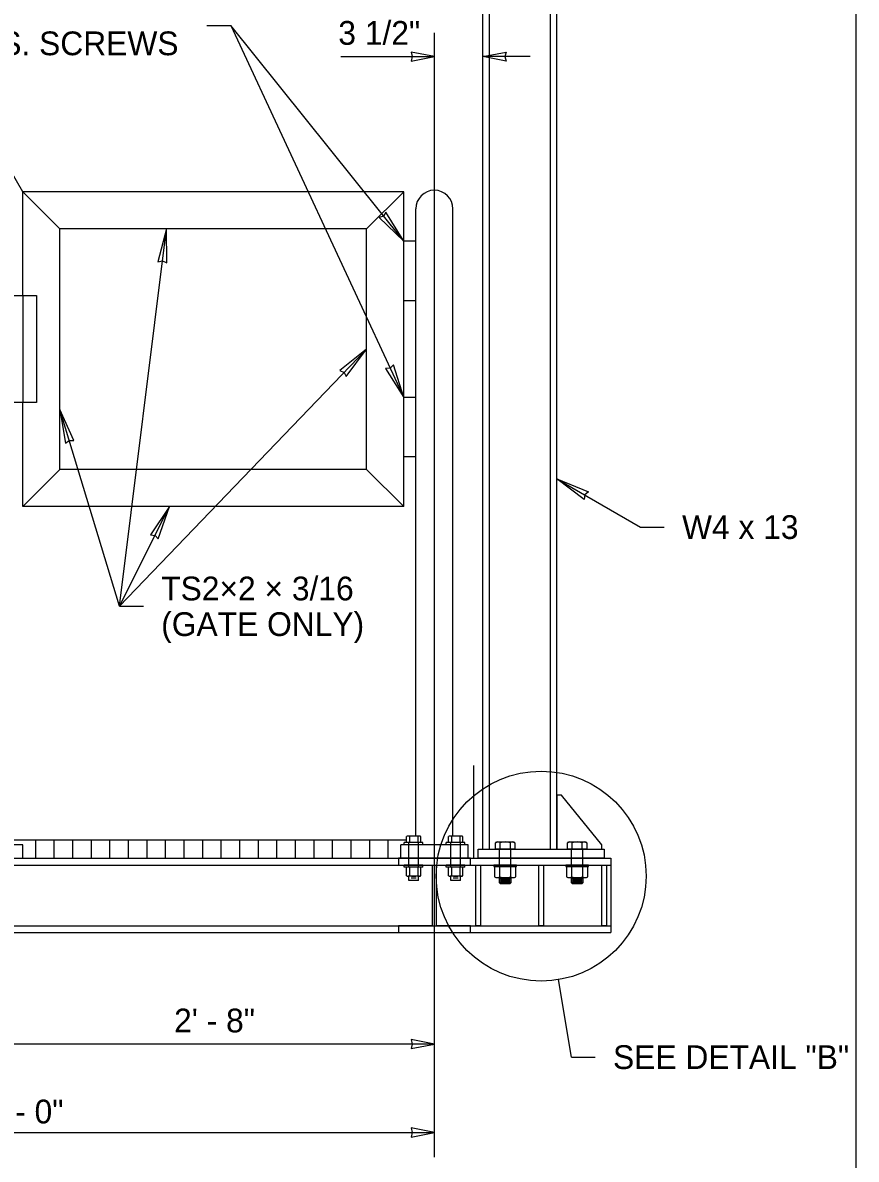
# Model space of a CAD drawing. Extents: x 99862 to 103151, y 100000 to 108076.
# Drawn here: x 102590 to 103151, y 100913 to 101679 of the extents above; entities that cross this region are included whole.
import ezdxf

# ---------------------------------------------------------------- set-up
doc = ezdxf.new("R2010")
doc.units = 0
for name, color, linetype in [('Level 1', 7, 'Continuous'), ('Level 13', 7, 'Continuous'), ('Level 15', 7, 'Continuous'), ('Level 2', 7, 'Continuous'), ('Level 20', 7, 'Continuous'), ('Level 30', 7, 'Continuous'), ('Level 36', 7, 'Continuous'), ('Level 4', 7, 'Continuous')]:
    doc.layers.add(name, color=color, linetype=linetype)

msp = doc.modelspace()

# ---------------------------------------------------------------- linework, layer by layer
at = {"layer": 'Level 1'}
msp.add_lwpolyline([(99862, 99999.5), (103151, 99999.5), (103151, 102075.5), (99862, 102075.5)], close=True, dxfattribs=at)
at = {"layer": 'Level 13'}
for p, q in [((102899.33, 101721.47), (102899.33, 101122.28)), ((102949.33, 101122.28), (102949.33, 101721.47)), ((102952.36, 101158.65), (102949.33, 101158.65)), ((102949.33, 101158.65), (102949.33, 101122.28)), ((102979.64, 101125.31), (102952.36, 101158.65)), ((102949.33, 101122.28), (102979.64, 101122.28)), ((102979.64, 101122.28), (102979.64, 101125.31)), ((102985.7, 101116.22), (102985.7, 101066.22))]:
    msp.add_line(p, q, dxfattribs=at)
msp.add_lwpolyline([(102896.3, 101122.28), (102981.15, 101122.28), (102981.15, 101116.22), (102896.3, 101116.22)], close=True, dxfattribs=at)
at = {"layer": 'Level 15'}
for p, q in [((102713.59, 101677.27), (102729.59, 101677.27)), ((102866.83, 100914.85), (102866.83, 101672.31)), ((102803.75, 101656.31), (102866.83, 101656.31)), ((102931.33, 101656.31), (102899.33, 101656.31)), ((102589.52, 101565.31), (102558.88, 101618.38)), ((102654.79, 101285.98), (102686.42, 101540.31)), ((102654.79, 101285.98), (102821.15, 101459.28)), ((102654.79, 101285.98), (102614.52, 101418.59)), ((102949.33, 101371.88), (103005.63, 101339.38)), ((102654.79, 101285.98), (102688.34, 101353.24)), ((103005.62, 101339.38), (103021.62, 101339.38)), ((102654.79, 101285.98), (102670.79, 101285.98)), ((102959.14, 100982.27), (102950.41, 101034.46)), ((102866.83, 100991.1), (102566.83, 100991.1)), ((102959.14, 100982.27), (102975.14, 100982.27)), ((102308.84, 100931.49), (102866.84, 100931.49))]:
    msp.add_line(p, q, dxfattribs=at)
msp.add_lwpolyline([(102846.15, 101531.9), (102729.59, 101677.27), (102846.15, 101426.67)], dxfattribs=at)
for points in [[(102866.84, 101656.31), (102851.11, 101659.39), (102851.84, 101656.31), (102851.11, 101653.23)], [(102899.34, 101656.31), (102915.06, 101659.39), (102914.33, 101656.31), (102915.06, 101653.23)], [(102846.15, 101531.91), (102834.2, 101551.58), (102832.53, 101548.89), (102829.54, 101547.85)], [(102686.42, 101540.31), (102680.64, 101518.02), (102683.73, 101518.7), (102686.57, 101517.29)], [(102821.15, 101459.28), (102803.18, 101444.87), (102806.07, 101443.57), (102807.49, 101440.74)], [(102846.15, 101426.67), (102839.23, 101448.63), (102836.96, 101446.41), (102833.81, 101446.11)], [(102614.52, 101418.6), (102618.3, 101395.88), (102620.85, 101397.76), (102624.01, 101397.62)], [(102949.33, 101371.88), (102970.6, 101363.05), (102968.19, 101360.99), (102967.61, 101357.88)], [(102688.34, 101353.24), (102675.48, 101334.15), (102678.62, 101333.76), (102680.82, 101331.48)], [(102866.83, 100991.1), (102851.11, 100994.18), (102851.84, 100991.1), (102851.11, 100988.01)], [(102866.83, 100931.49), (102851.11, 100934.58), (102851.84, 100931.49), (102851.11, 100928.41)]]:
    msp.add_lwpolyline(points, close=True, dxfattribs=at)
msp.add_circle((102938.75, 101104.21), 70.72, dxfattribs=at)
at = {"layer": 'Level 2'}
for p, q in [((102589.52, 101565.31), (102614.52, 101540.31)), ((102846.15, 101565.31), (102821.15, 101540.31))]:
    msp.add_line(p, q, dxfattribs=at)
at = {"layer": 'Level 30'}
for p, q in [((102911.21, 101122.28), (102911.21, 101126.69)), ((102917.76, 101126.69), (102917.76, 101122.28)), ((102959.69, 101122.28), (102959.69, 101126.69)), ((102966.25, 101126.69), (102966.25, 101122.28)), ((102910.93, 101103.75), (102910.93, 101110.65)), ((102918.04, 101110.65), (102918.04, 101103.75)), ((102959.42, 101103.75), (102959.42, 101110.65)), ((102966.53, 101110.65), (102966.53, 101103.75)), ((102909.16, 101103.19), (102919.82, 101103.19)), ((102910.7, 101102.48), (102918.27, 101102.48)), ((102910.7, 101101.06), (102918.27, 101101.06)), ((102918.27, 101099.64), (102910.7, 101099.64)), ((102911.41, 101101.77), (102917.56, 101101.77)), ((102911.41, 101100.35), (102917.56, 101100.35)), ((102957.64, 101103.19), (102968.3, 101103.19)), ((102959.18, 101102.48), (102966.76, 101102.48)), ((102959.18, 101101.06), (102966.76, 101101.06)), ((102966.76, 101099.64), (102959.18, 101099.64)), ((102959.89, 101101.77), (102966.05, 101101.77)), ((102959.89, 101100.35), (102966.05, 101100.35))]:
    msp.add_line(p, q, dxfattribs=at)
for points in [[(102920.17, 101127.25), (102921.05, 101126.75), (102921.05, 101122.28), (102907.92, 101122.28), (102907.92, 101126.75), (102908.8, 101127.25), (102920.17, 101127.25)], [(102968.65, 101127.25), (102969.53, 101126.75), (102969.53, 101122.28), (102956.41, 101122.28), (102956.41, 101126.75), (102957.29, 101127.25), (102968.65, 101127.25)], [(102906.91, 101111.68), (102906.91, 101110.65), (102922.06, 101110.65), (102922.06, 101111.68), (102906.91, 101111.68)], [(102921.6, 101103.75), (102921.6, 101110.65), (102907.38, 101110.65), (102907.38, 101103.75)], [(102955.4, 101111.68), (102955.4, 101110.65), (102970.55, 101110.65), (102970.55, 101111.68), (102955.4, 101111.68)], [(102970.08, 101103.75), (102970.08, 101110.65), (102955.86, 101110.65), (102955.86, 101103.75)], [(102918.27, 101103.19), (102918.27, 101099.64), (102917.56, 101098.93), (102911.41, 101098.93), (102910.7, 101099.64), (102910.7, 101103.19)], [(102966.76, 101103.19), (102966.76, 101099.64), (102966.05, 101098.93), (102959.89, 101098.93), (102959.18, 101099.64), (102959.18, 101103.19)]]:
    msp.add_lwpolyline(points, dxfattribs=at)
for centre, radius, start, end in [((102909.53, 101124.48), 2.78, 52.82514, 125.17414), ((102914.49, 101117.45), 9.81, 70.46322, 109.53678), ((102919.45, 101124.48), 2.78, 54.82585, 127.17486), ((102958.01, 101124.48), 2.78, 52.82514, 125.17414), ((102962.97, 101117.45), 9.81, 70.46322, 109.53678), ((102967.93, 101124.48), 2.78, 54.82585, 127.17486), ((102909.16, 101106.27), 3.08, 234.73561, 305.26439), ((102914.49, 101115.5), 12.31, 253.22134, 286.77866), ((102919.82, 101106.27), 3.08, 234.73561, 305.26439), ((102957.64, 101106.27), 3.08, 234.73561, 305.26439), ((102962.97, 101115.5), 12.31, 253.22134, 286.77866), ((102968.3, 101106.27), 3.08, 234.73561, 305.26439)]:
    msp.add_arc(centre, radius, start, end, dxfattribs=at)
at = {"layer": 'Level 36'}
for p, q in [((102589.52, 101495.34), (102589.52, 101423.21)), ((102910.7, 101111.68), (102910.7, 101122.28)), ((102918.27, 101111.68), (102918.27, 101122.28)), ((102959.18, 101111.68), (102959.18, 101122.28)), ((102966.76, 101111.68), (102966.76, 101122.28)), ((102842.59, 101111.67), (102865.32, 101111.67)), ((102865.32, 101111.67), (102865.32, 101070.77)), ((102868.35, 101070.77), (102868.35, 101111.67)), ((102868.35, 101111.67), (102891.07, 101111.67)), ((102865.32, 101070.77), (102842.59, 101070.77)), ((102891.07, 101070.77), (102868.35, 101070.77))]:
    msp.add_line(p, q, dxfattribs=at)
for points in [[(102891.07, 101111.67), (102891.07, 101116.22), (102842.59, 101116.22), (102842.59, 101111.67)], [(102842.59, 101070.77), (102842.59, 101066.22), (102891.07, 101066.22), (102891.07, 101070.77)]]:
    msp.add_lwpolyline(points, dxfattribs=at)
at = {"layer": 'Level 4'}
for p, q in [((102903.88, 101122.28), (102903.88, 101721.47)), ((102944.79, 101721.47), (102944.79, 101122.28)), ((102846.15, 101565.31), (102589.52, 101565.31)), ((102589.52, 101495.34), (102589.52, 101565.31)), ((102846.15, 101353.24), (102846.15, 101565.31)), ((102854.34, 101178.72), (102854.34, 101553.81)), ((102879.33, 101178.72), (102879.33, 101553.81)), ((102821.15, 101540.31), (102614.52, 101540.31)), ((102614.52, 101378.24), (102614.52, 101540.31)), ((102821.15, 101378.24), (102821.15, 101540.31)), ((102854.34, 101531.9), (102846.15, 101531.9)), ((102854.34, 101491.9), (102846.15, 101491.9)), ((102854.34, 101426.67), (102846.15, 101426.67)), ((102589.52, 101353.24), (102589.52, 101423.21)), ((102854.34, 101386.67), (102846.15, 101386.67)), ((102589.52, 101353.24), (102614.52, 101378.24)), ((102821.15, 101378.24), (102614.52, 101378.24)), ((102846.15, 101353.24), (102821.15, 101378.24)), ((102846.15, 101353.24), (102589.52, 101353.24)), ((102854.34, 101131.15), (102854.34, 101178.72)), ((102879.33, 101131.15), (102879.33, 101178.72)), ((102893.35, 101116.22), (102893.35, 101178.72)), ((102339.89, 101128.72), (102847.95, 101128.72)), ((102598.28, 101116.22), (102598.28, 101128.72)), ((102610.78, 101116.22), (102610.78, 101128.72)), ((102623.28, 101116.22), (102623.28, 101128.72)), ((102635.78, 101116.22), (102635.78, 101128.72)), ((102648.28, 101116.22), (102648.28, 101128.72)), ((102660.78, 101116.22), (102660.78, 101128.72)), ((102673.28, 101116.22), (102673.28, 101128.72)), ((102685.78, 101116.22), (102685.78, 101128.72)), ((102698.28, 101116.22), (102698.28, 101128.72)), ((102710.78, 101116.22), (102710.78, 101128.72)), ((102723.28, 101116.22), (102723.28, 101128.72)), ((102735.78, 101116.22), (102735.78, 101128.72)), ((102748.28, 101116.22), (102748.28, 101128.72)), ((102760.78, 101116.22), (102760.78, 101128.72)), ((102773.28, 101116.22), (102773.28, 101128.72)), ((102785.78, 101116.22), (102785.78, 101128.72)), ((102798.28, 101116.22), (102798.28, 101128.72)), ((102810.78, 101116.22), (102810.78, 101128.72)), ((102823.28, 101116.22), (102823.28, 101128.72)), ((102835.78, 101116.22), (102835.78, 101128.72)), ((102847.95, 101126.82), (102847.95, 101130.82)), ((102856.68, 101131.15), (102848.98, 101131.15)), ((102850.01, 101130.82), (102850.01, 101126.82)), ((102855.63, 101130.82), (102855.63, 101126.82)), ((102857.69, 101126.82), (102857.69, 101130.82)), ((102876.24, 101126.82), (102876.24, 101130.82)), ((102884.97, 101131.15), (102877.27, 101131.15)), ((102878.3, 101130.82), (102878.3, 101126.82)), ((102883.92, 101130.82), (102883.92, 101126.82)), ((102885.98, 101126.82), (102885.98, 101130.82)), ((102589.56, 101125.31), (102544.11, 101125.31)), ((102589.56, 101116.22), (102589.56, 101125.31)), ((102889.56, 101125.31), (102844.11, 101125.31)), ((102844.11, 101116.22), (102844.11, 101125.31)), ((102858.97, 101126.82), (102846.49, 101126.82)), ((102846.49, 101125.31), (102846.49, 101126.82)), ((102857.69, 101126.82), (102847.95, 101126.82)), ((102849.57, 101110.16), (102849.57, 101126.82)), ((102856.07, 101110.16), (102856.07, 101126.82)), ((102858.97, 101125.31), (102858.97, 101126.82)), ((102887.26, 101126.82), (102874.78, 101126.82)), ((102874.78, 101125.31), (102874.78, 101126.82)), ((102885.98, 101126.82), (102876.24, 101126.82)), ((102877.87, 101110.16), (102877.87, 101126.82)), ((102884.36, 101110.16), (102884.36, 101126.82)), ((102887.26, 101125.31), (102887.26, 101126.82)), ((102889.56, 101116.22), (102889.56, 101125.31)), ((102282.32, 101116.22), (102985.7, 101116.22)), ((102282.32, 101111.67), (102985.7, 101111.67)), ((102846.49, 101110.16), (102846.49, 101111.67)), ((102858.97, 101111.67), (102846.49, 101111.67)), ((102858.97, 101110.16), (102846.49, 101110.16)), ((102857.69, 101110.16), (102847.95, 101110.16)), ((102847.95, 101104.48), (102847.95, 101110.16)), ((102850.01, 101110.16), (102850.01, 101104.48)), ((102855.63, 101110.16), (102855.63, 101104.48)), ((102857.69, 101104.48), (102857.69, 101110.16)), ((102858.97, 101110.16), (102858.97, 101111.67)), ((102874.78, 101110.16), (102874.78, 101111.67)), ((102887.26, 101111.67), (102874.78, 101111.67)), ((102887.26, 101110.16), (102874.78, 101110.16)), ((102885.98, 101110.16), (102876.24, 101110.16)), ((102876.24, 101104.48), (102876.24, 101110.16)), ((102878.3, 101110.16), (102878.3, 101104.48)), ((102883.92, 101110.16), (102883.92, 101104.48)), ((102885.98, 101104.48), (102885.98, 101110.16)), ((102887.26, 101110.16), (102887.26, 101111.67)), ((102856.68, 101104.15), (102848.98, 101104.15)), ((102849.57, 101101.23), (102849.57, 101104.15)), ((102856.07, 101101.23), (102849.57, 101101.23)), ((102854.55, 101102.74), (102851.09, 101102.74)), ((102856.07, 101101.23), (102856.07, 101104.15)), ((102884.97, 101104.15), (102877.27, 101104.15)), ((102877.87, 101101.23), (102877.87, 101104.15)), ((102884.36, 101101.23), (102877.87, 101101.23)), ((102882.85, 101102.74), (102879.38, 101102.74)), ((102884.36, 101101.23), (102884.36, 101104.15)), ((102282.32, 101070.77), (102985.7, 101070.77)), ((102282.32, 101066.22), (102985.7, 101066.22))]:
    msp.add_line(p, q, dxfattribs=at)
for points in [[(102568.82, 101495.34), (102598.85, 101495.34), (102598.85, 101423.21), (102568.82, 101423.21)], [(102894.81, 101111.68), (102897.84, 101111.68), (102897.84, 101070.77), (102894.81, 101070.77)], [(102937.23, 101111.68), (102940.26, 101111.68), (102940.26, 101070.77), (102937.23, 101070.77)], [(102979.66, 101111.68), (102982.69, 101111.68), (102982.69, 101070.77), (102979.66, 101070.77)]]:
    msp.add_lwpolyline(points, close=True, dxfattribs=at)
for centre, radius, start, end in [((102866.83, 101553.81), 12.5, 0, 180), ((102848.98, 101129.37), 1.78, 54.71987, 125.28013), ((102852.82, 101118.88), 12.27, 76.75036, 103.24964), ((102856.66, 101129.37), 1.78, 54.71987, 125.28013), ((102877.27, 101129.37), 1.78, 54.71987, 125.28013), ((102881.11, 101118.88), 12.27, 76.75036, 103.24964), ((102884.95, 101129.37), 1.78, 54.71987, 125.28013), ((102848.98, 101105.93), 1.78, 234.71987, 305.28013), ((102852.82, 101116.42), 12.27, 256.75036, 283.24964), ((102856.66, 101105.93), 1.78, 234.71987, 305.28013), ((102877.27, 101105.93), 1.78, 234.71987, 305.28013), ((102881.11, 101116.42), 12.27, 256.75036, 283.24964), ((102884.95, 101105.93), 1.78, 234.71987, 305.28013)]:
    msp.add_arc(centre, radius, start, end, dxfattribs=at)

# ---------------------------------------------------------------- texts
at = {"layer": 'Level 20'}
for s, p in [('3 1/2" ', (102802.09, 101664.31)), ('1/4" (IN) S.S. SCREWS', (102469.31, 101657.27)), ('W4 x 13', (103033.64, 101331.38)), ('TS2×2 × 3/16', (102682.8, 101289.99)), ('(GATE ONLY)', (102682.8, 101265.99)), ('2\' - 8"', (102691.5, 100998.93)), ('SEE DETAIL "B"', (102987.15, 100974.27)), ('5\' - 0"', (102562.5, 100937.61))]:
    msp.add_text(s, height=16, dxfattribs=at).set_placement(p)

doc.saveas('drawing.dxf')
